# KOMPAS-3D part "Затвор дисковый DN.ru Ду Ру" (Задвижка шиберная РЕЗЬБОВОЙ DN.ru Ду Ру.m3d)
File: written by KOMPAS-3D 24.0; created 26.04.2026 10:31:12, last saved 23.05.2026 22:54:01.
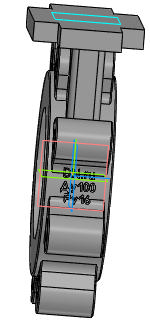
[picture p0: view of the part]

Document properties: Автор: R2D2; Полное имя файла: E:\Работа\Зайцев\GVKR1331M-1W-Fb-2P Задвижка шиберная с выдвижным штоком DN.ru Ду50-300 Ру16-10-6 с пневмоприводом\исходные материалы\DN100\Задвижка шиберная РЕЗЬБОВОЙ DN.ru Ду Ру.m3d

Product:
- Part/product: Затвор дисковый DN.ru Ду Ру
    Масса: 18.2
    Раздел спецификации: Прочие изделия
    Примечание: D050-23732

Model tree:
1. Смещенная плоскость:2
2. Диск
3. Корпус
4. Элемент выдавливания:3
     Расстояние 1 = 30
5. Элемент вращения:1
     Угол 1 = 360
6. Корпус штока
7. Элемент выдавливания:6  (with: Грань.Элемент вращения:1)
     Расстояние 1 = 120
8. Ушко  (with: Ребро.Элемент вращения:1)
9. Элемент выдавливания:5
10. Скругление:7  (with: Ребро.Элемент выдавливания:5)
     Радиус = 1
11. Эскиз:1  (with: Ребро.Элемент выдавливания:5)
12. Элемент выдавливания:12
     Расстояние 1 = 25.5
13. Элемент выдавливания:13
14. Массив по концентрической сетке:1  (with: Элемент выдавливания:13, Элемент выдавливания:12, Элемент выдавливания:5, Скругление:7)  (8 pattern instances)
     Шаг 2 = 360
15. Эскиз:2  (labels: Ребро.Элемент выдавливания:5.Экземпляр ( 1, 3 ); Ребро.Элемент выдавливания:5.Экземпляр ( 1, 6 ))
16. Элемент выдавливания:14
17. площадка  (with: Грань.Элемент выдавливания:6)
18. Элемент выдавливания:15
     Расстояние 2 = 15
19. Скругление:10  (with: Ребро.Элемент выдавливания:6)
     Радиус = 5
20. Эскиз:4  (labels: Задвижка шиберная с выдвижным штоком DN.ru Ду50 Ру16; Затвор дисковый DN.ru Ду200 Ру16)
21. Элемент выдавливания:16  (with: Грань.Элемент вращения:1)
     Расстояние 1 = 79; Смещение 1 = 1
22. Эскиз:5  (labels: Задвижка шиберная DN.ru Ду50 Ру10; Затвор дисковый DN.ru Ду200 Ру16)
23. Элемент выдавливания:17  (with: Грань.Элемент вращения:1)
     Расстояние 1 = 79.998; Смещение 1 = 2
24. Скругление:8  (with: Ребро.Элемент вращения:1)
     Радиус = 1

Expressions: 360/n; c-8-2*t; v1301/2; d/2+30; dd/2
Referenced files in E:\Работа\Зайцев\GVKR1331E-1W-Fb-2P Задвижка шиберная DN.ru Ду50-300 Ру16-10-6\исходные материалы\DN50\: GVKR1331E-1W-Fb-2P Задвижка шиберная с выдвижным штоком DN.ru Ду50 Ру16.a3d, GVKR1331E-1W-Fb-2P Задвижка шиберная DN.ru Ду50 Ру16.a3d
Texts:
  Угловой размер с обрывом
  GOST 26.020 Pr3
  var3D
  ширина затвора по металлу
  площадка под крепеж
  DN+10
  dk+20
  dk-10
  Плоскость ZY.Начало координат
